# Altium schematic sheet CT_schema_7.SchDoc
size 274 x 160 mm
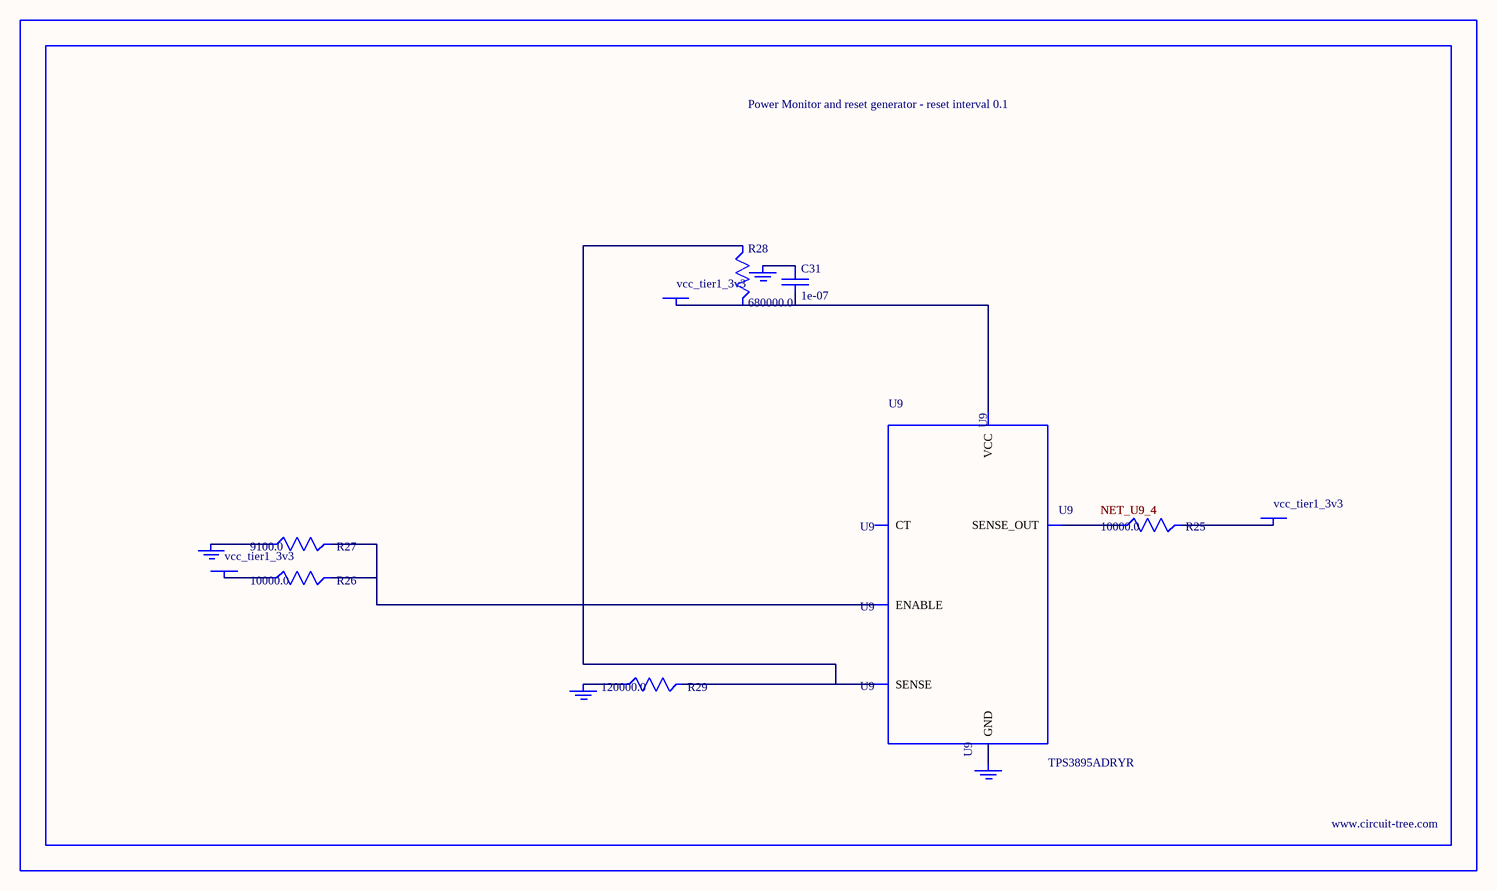
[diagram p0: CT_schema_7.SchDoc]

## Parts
BORDER6  (no value)
C31  1e-07  [C0402]
GND_INSTANCE_6_0  (no value)
GND_INSTANCE_6_1  (no value)
GND_INSTANCE_6_2  (no value)
GND_INSTANCE_6_3  (no value)
POWER_INSTANCE_6_0  vcc_tier1_3v3
POWER_INSTANCE_6_1  vcc_tier1_3v3
POWER_INSTANCE_6_2  vcc_tier1_3v3
R25  10000.0  [R0603]
R26  10000.0  [R0603]
R27  9100.0  [R0603]
R28  680000.0  [R0603]
R29  120000.0  [R0603]
U9  TPS3895ADRYR  [SON-6]

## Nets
NetC31_1: C31.1 GND_INSTANCE_6_2.0(GND)
NetC31_2: C31.2 POWER_INSTANCE_6_2.0(PWR) R28.2 U9.6(VCC)
NetGND_INSTANCE_6_0_0: GND_INSTANCE_6_0.0(GND) R27.1
NetGND_INSTANCE_6_1_0: GND_INSTANCE_6_1.0(GND) R29.1
NetGND_INSTANCE_6_3_0: GND_INSTANCE_6_3.0(GND) U9.2(GND)
NetPOWER_INSTANCE_6_0_0: POWER_INSTANCE_6_0.0(PWR) R26.1
NetPOWER_INSTANCE_6_1_0: POWER_INSTANCE_6_1.0(PWR) R25.2
NetR25_1: R25.1 U9.4(SENSE_OUT)
NetR26_2: R26.2 R27.2 U9.1(ENABLE)
NetR28_1: R28.1 R29.2 U9.3(SENSE)

Not connected (* = marked no-connect by the designer): U9 5(CT)

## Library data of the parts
BORDER6 = BORDER_PAGE6
C31 = C0402C104K3RACTU
GND_INSTANCE_6_0-GND_INSTANCE_6_3 = GND
POWER_INSTANCE_6_0-POWER_INSTANCE_6_2 = PWR
R25 R26 = RC0603JR-0710KL
R27 = RC0603JR-079K1L
R28 = RC0603JR-07680KL
R29 = RC0603JR-07120KL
